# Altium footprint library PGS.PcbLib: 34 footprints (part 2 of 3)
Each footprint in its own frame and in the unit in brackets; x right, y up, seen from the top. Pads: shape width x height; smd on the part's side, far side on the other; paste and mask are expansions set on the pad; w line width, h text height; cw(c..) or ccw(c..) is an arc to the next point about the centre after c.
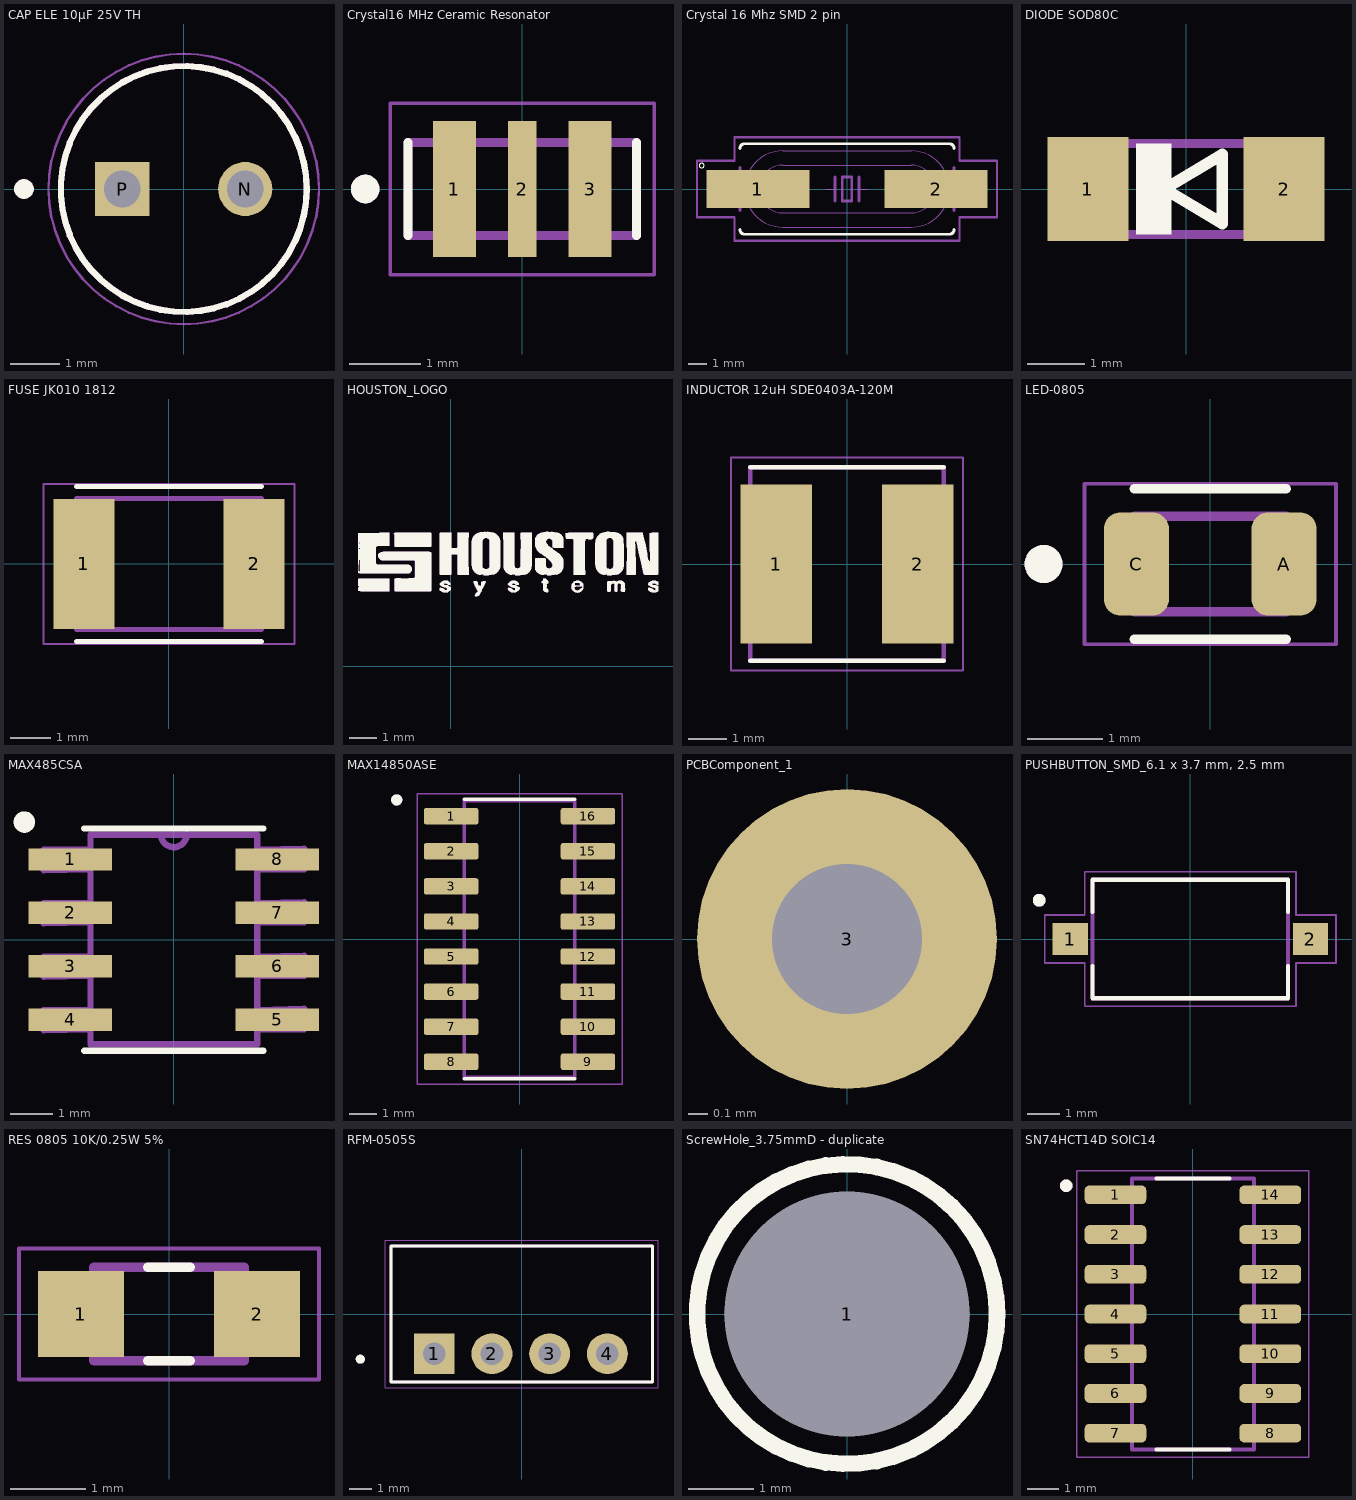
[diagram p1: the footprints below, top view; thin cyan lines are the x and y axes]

## CAP ELE 10µF 25V TH [mm] "10µF 25V Aluminum Electrolytic Capacitors Radial Lead Type THT, Dia-5mm, Pitch-2mm ECEA1EN100UI"
pads (2):
  round 1.1 hole 0.75: N(1.25,0)
  rect 1.1x1.1 hole 0.75: P(-1.25,0)
Top Overlay:
  circle w0.127: c0,0 r2.5
  circle w0.2: c-3.25,0 r0.1
Mechanical 13:
  circle w0.127: c0,0 r2.5
  circle w0.2: c-3.25,0 r0.1
Mechanical 15:
  circle w0.05: c0,0 r2.75
3D body "step_temp.STEP": height 11, standoff -17, extent -2.5,-2.498 2.5,2.498

## Crystal16 MHz Ceramic Resonator [mm] "Crystal 16 MHz Ceramic Resonator Built SMT in Capacitor 15 pF Â±0.3% -20Â°C ~ 80Â°C Surface Mount-CSTCE16M0V53-R0CSTCE16M0V53-R0"
pads (3):
  rect 0.6x1.9 smd: 1(-0.95,0) 3(0.95,0)
  rect 0.4x1.9 smd: 2(0,0)
Top Overlay:
  circle w0.2: c-2.2,0 r0.1
  lines w0.127: -1.6,-0.65 -1.6,0.65 ; 1.6,-0.65 1.6,0.65
Mechanical 13:
  circle w0.2: c-2.2,0 r0.1
  lines w0.127: -1.6,-0.65 1.6,-0.65 1.6,0.65 -1.6,0.65 -1.6,-0.65
Mechanical 15:
  lines w0.05: -1.85,-1.2 1.85,-1.2 1.85,1.2 -1.85,1.2 -1.85,-1.2
3D body "step_temp.STEP": height 1, standoff 0, extent -1.6,-0.65 1.6,0.65

## Crystal 16 Mhz SMD 2 pin [mm] "16 MHz Â±30ppm Crystal 20pF 60 Ohms HC-49/US FOXSDLF/128-20 16 Mhz Crystal SMD –CSM-4ALX(28ALX) SMT12.5mmX4.85mmX4mm"
pads (2):
  rect 5.5x2 smd: 1(-4.75,0) 2(4.75,0)
Top Overlay:
  circle w0: c-7.75,1.25 r0.127
  lines w0.152: -5.715,-2.159 ccw(c-5.461,-2.159) -5.461,-2.413 5.461,-2.413 ccw(c5.461,-2.159) 5.715,-2.159 ; -5.715,2.159 cw(c-5.461,2.159) -5.461,2.413 5.461,2.413 cw(c5.461,2.159) 5.715,2.159
Mechanical 13:
  lines w0.051: -1.143,0 -0.635,0 ; 0.635,0 1.143,0 ; -5.114,-1.136 ccw(c-3.429,0) -3.429,-2.032 3.429,-2.032 ccw(c3.429,0) 5.113,-1.136 ccw(c3.429,0) 5.114,1.136 ccw(c3.429,0) 3.429,2.032 -3.429,2.032 ccw(c-3.429,0) -5.114,1.136 ccw(c-3.429,0) -5.114,-1.136 ; -3.986,-1.141 ccw(c-3.429,0) -3.429,-1.27 3.429,-1.27 ccw(c3.429,0) 3.986,-1.141 ccw(c3.429,0) 3.986,1.141 ccw(c3.429,0) 3.429,1.27 -3.429,1.27 ccw(c-3.429,0) -3.986,1.141 ccw(c-3.429,0) -3.986,-1.141
  lines w0.152: -5.715,-1.143 -5.715,1.143 ; -5.715,-0.381 -6.477,-0.381 -6.477,0.381 -5.715,0.381 ; -0.635,-0.635 -0.635,0 -0.635,0.635 ; 0.635,-0.635 0.635,0 0.635,0.635 ; 5.715,-1.143 5.715,-0.381 ; 5.715,1.143 5.715,0.381 ; 5.715,-0.381 5.715,0.381 ; 5.715,-0.381 6.477,-0.381 6.477,0.381 5.715,0.381 ; -0.254,-0.635 -0.254,0.635 0.254,0.635 0.254,-0.635 -0.254,-0.635
Mechanical 15:
  lines w0.127: -8,-1.5 -8,1.5 -6,1.5 -6,2.75 6,2.75 6,1.5 8,1.5 8,-1.5 6,-1.5 6,-2.75 -6,-2.75 -6,-1.5 -8,-1.5
3D body "step_temp.STEP": height 4.5, standoff 0, extent -6.75,-2.5 6.75,2.5

## DIODE SOD80C [mm] "Diode Standard 75V 200mA _DC_ SMT LLDS; MiniMelf DIODE SOD80C PMLL4148L"
pads (2):
  rect 1.4x1.8 smd: 1(-1.7,0) 2(1.7,0)
Top Overlay:
  region: -0.254,-0.788 -0.864,-0.788 -0.864,0.787 -0.254,0.787
  lines w0.203: -0.373,0 0.627,0.6 0.627,-0.6 -0.373,0
Mechanical 13:
  region: -1.295,-0.865 -1.857,-0.865 -1.857,0.864 -1.295,0.864
  region: 1.854,-0.865 1.298,-0.865 1.298,0.864 1.854,0.864
  lines w0.152: -1.321,-0.787 1.321,-0.787 ; -1.321,0.787 1.321,0.787
3D body "BZT55C75-GS08.STEP": height 0.8, standoff -0.8, extent -1.75,-0.762 1.75,0.805

## FUSE JK010 1812 [mm] "FUSE JK010 Polymeric PTC Resettable Fuse 60V 100 mA 0.8W Ih SMT 1812 (4532 Metric), Concave HUAAN MF-MSMF010-60V"
pads (2):
  rect 1.5x3.2 smd: 1(-2.1,0) 2(2.1,0)
Top Overlay:
  lines w0.127: -2.275,-1.913 2.275,-1.913 ; -2.275,1.913 2.275,1.913
Mechanical 13:
  lines w0.127: -2.275,-1.62 -2.275,1.62 2.275,1.62 2.275,-1.62 -2.275,-1.62
Mechanical 15:
  lines w0.05: -3.1,-1.977 3.1,-1.977 3.1,1.977 -3.1,1.977 -3.1,-1.977
3D body "step_temp.STEP": height 0.85, standoff 0, extent -2.275,-1.62 2.275,1.62

## HOUSTON_LOGO [mm]
Top Overlay:
  drawing of 26 lines, arcs and shapes, not listed
Mechanical 13:
  drawing of 26 lines, arcs and shapes, not listed

## INDUCTOR 12uH SDE0403A-120M [mm] "INDUCTOR_2020(5.5mmX4.5mm)  SMT INDUCTOR 12uH SDE0403A-120M LQH5BPB4R7NT0L"
pads (2):
  rect 1.85x4.1 smd: 1(-1.825,0) 2(1.825,0)
Top Overlay:
  lines w0.127: -2.5,-2.5 2.5,-2.5 ; -2.5,2.5 2.5,2.5
Mechanical 13:
  lines w0.127: -2.5,-2.5 2.5,-2.5 2.5,2.5 -2.5,2.5 -2.5,-2.5
Mechanical 15:
  lines w0.05: -3,-2.75 3,-2.75 3,2.75 -3,2.75 -3,-2.75
3D body "LQH5BPN100M38L.STEP": height 4, standoff 0, extent -2.45,-2.45 2.45,2.45

## LED-0805 [mm] "Red 640nm LED Indication - Discrete 1.85V 0805 (2012 Metric) SMT APT2012SRCPRV"
pads (2):
  rrect50% 0.86x1.36 smd: A(0.975,0) C(-0.975,0)
Top Overlay:
  circle w0.3: c-2.2,0 r0.1
  lines w0.127: -1,-0.995 1,-0.995 ; -1,0.995 1,0.995
Mechanical 13:
  circle w0.3: c-2.2,0 r0.1
  lines w0.127: -1,-0.63 1,-0.63 1,0.63 -1,0.63 -1,-0.63
Mechanical 15:
  lines w0.05: -1.66,-1.059 1.66,-1.059 1.66,1.059 -1.66,1.059 -1.66,-1.059
3D body "step_temp.STEP": height 0.75, standoff 0, extent -1,-0.625 1,0.625

## MAX485CSA [mil] "MAX485CSA-RS-485/RS-422 Transceivers, SOIC-8 SMT"
pads (8):
  rect 78x21 smd: 1(-97,75) 2(-97,25) 3(-97,-25) 4(-97,-75) 5(97,-75) 6(97,-25) 7(97,25) 8(97,75)
Top Overlay:
  circle w10: c-140,110 r5
  lines w6: -84,-104 84,-104 ; -84,104 84,104
Mechanical 13:
  lines w6: -12,98.08 ccw(c0,98.5) 12,98.92 ; -122,-85 -78,-84 -78,-66 -122,-66 -122,-85 ; -122,-35 -78,-34 -78,-16 -122,-16 -122,-35 ; -122,15 -78,16 -78,34 -122,34 -122,15 ; -122,65 -78,66 -78,84 -122,84 -122,65 ; -78,-98 -78,98 -12,98 78,98 78,-98 -78,-98 ; 78,-84 122,-84 122,-65 78,-66 78,-84 ; 78,-34 122,-34 122,-15 78,-16 78,-34 ; 78,16 122,16 122,35 78,34 78,16 ; 78,66 122,66 122,85 78,84 78,66
3D body "step_temp.STEP": height 68.9, standoff 0, extent -118.11,-96.46 118.11,96.46

## MAX14850ASE [mm] "MAX14850ASE SOIC16 Six-Channel SMT Digital Isolator SOIC127P600X175-16N"
pads (16):
  rrect25% 1.97x0.59 smd: 1(-2.475,4.445) 2(-2.475,3.175) 3(-2.475,1.905) 4(-2.475,0.635) 5(-2.475,-0.635) 6(-2.475,-1.905) 7(-2.475,-3.175) 8(-2.475,-4.445) 9(2.475,-4.445) 10(2.475,-3.175) 11(2.475,-1.905) 12(2.475,-0.635) 13(2.475,0.635) 14(2.475,1.905) 15(2.475,3.175) 16(2.475,4.445)
Top Overlay:
  circle w0.2: c-4.445,5.035 r0.1
  lines w0.127: -2,-5.06 2,-5.06 ; -2,5.06 2,5.06
Mechanical 13:
  circle w0.2: c-4.445,5.035 r0.1
  lines w0.127: -2,-5 2,-5 2,5 -2,5 -2,-5
Mechanical 15:
  lines w0.05: -3.71,-5.25 3.71,-5.25 3.71,5.25 -3.71,5.25 -3.71,-5.25
3D body "step_temp.STEP": height 1.75, standoff 0, extent -3,-4.95 3,4.95

## PCBComponent_1 [mil]
pads (1):
  round 60 hole 30: 3(0,0)

## PUSHBUTTON_SMD_6.1 x 3.7 mm, 2.5 mm [mm] "6.1 x 3.7 mm, 2.5 mm Actuator Height, 260 gf, Red, SMT, SPST, Tactile Switch, TS09-63-25-R-260-SMT-TR"
height 2.5
pads (2):
  rect 1.1x1 smd: 1(-3.75,0) 2(3.75,0)
Top Overlay:
  circle w0.2: c-4.72,1.21 r0.1
  lines w0.127: -3.05,-0.85 -3.05,-1.85 3.05,-1.85 3.05,-0.85 ; -3.05,0.85 -3.05,1.85 3.05,1.85 3.05,0.85
Mechanical 13:
  circle w0.2: c-4.72,1.21 r0.1
  lines w0.127: -3.05,-1.85 3.05,-1.85 3.05,1.85 -3.05,1.85 -3.05,-1.85
Mechanical 15:
  lines w0.05: -4.55,-0.75 -4.55,0.75 -3.3,0.75 -3.3,2.1 3.3,2.1 3.3,0.75 4.55,0.75 4.55,-0.75 3.3,-0.75 3.3,-2.1 -3.3,-2.1 -3.3,-0.75 -4.55,-0.75
3D body "step_temp.STEP": height 2.5, standoff -0.05, extent -4.05,-1.85 4.05,1.85

## RES 0805 10K/0.25W 5% [mm] "RESISTOR, THICK FILM, 10K, 5%, 0805, SMT FULL REEL Product Range:PANASONIC - ERJ Series"
height 0.55
pads (2):
  rect 1.15x1.15 smd: 1(-1.175,0) 2(1.175,0)
Top Overlay:
  lines w0.127: -0.28,-0.625 0.28,-0.625 ; -0.28,0.625 0.28,0.625
Mechanical 13:
  lines w0.127: -1,-0.625 -1,0.625 1,0.625 1,-0.625 -1,-0.625
Mechanical 15:
  lines w0.05: -2,-0.875 -2,0.875 2,0.875 2,-0.875 -2,-0.875
3D body "step_temp.STEP": height 0.7, standoff 0, extent -1,-0.625 1,0.625

## RFM-0505S [mm] "DC-DC Converter/Isolator, SIP4, THT S/T 1kV unreg, Single Output, 1W, 5V Out, RFM Series RFM-0505S"
height 10
pads (4):
  rect 1.8x1.8 hole 1: 1(-3.85,-1.75)
  round 1.8 hole 1: 2(-1.31,-1.75) 3(1.23,-1.75) 4(3.77,-1.75)
Top Overlay:
  circle w0.2: c-7.11,-1.99 r0.1
  lines w0.127: -5.75,-3 5.75,-3 5.75,3 -5.75,3 -5.75,-3
Mechanical 13:
  circle w0.2: c-7.1,-1.99 r0.1
  lines w0.127: -5.75,-3 5.75,-3 5.75,3 -5.75,3 -5.75,-3
Mechanical 15:
  lines w0.05: -6,-3.25 6,-3.25 6,3.25 -6,3.25 -6,-3.25
3D body "step_temp.STEP": height 9.5, standoff -4.6, extent -5.75,-3 5.75,3

## ScrewHole_3.75mmD - duplicate [mm] "SCREW HEAD DIA 4.5MM, SREW LEG DIA 3 MM"
pads (1):
  round 3.75 hole 3.75 unplated: 1(0,0)
Top Overlay:
  circle w0.254: c0,0 r2.3

## SN74HCT14D SOIC14 [mm] "SN74HCT14D SOIC14 6-ch, 4.5V to 5.5V SMT inverters with Schmitt-Trigger inputs"
pads (14):
  rrect50% 1.97x0.6 smd: 1(-2.475,3.81) 2(-2.475,2.54) 3(-2.475,1.27) 4(-2.475,0) 5(-2.475,-1.27) 6(-2.475,-2.54) 7(-2.475,-3.81) 8(2.475,-3.81) 9(2.475,-2.54) 10(2.475,-1.27) 11(2.475,0) 12(2.475,1.27) 13(2.475,2.54) 14(2.475,3.81)
Top Overlay:
  circle w0.2: c-4.05,4.1 r0.1
  lines w0.127: -1.17,-4.325 1.17,-4.325 ; -1.17,4.325 1.17,4.325
Mechanical 13:
  circle w0.2: c-4.05,4.1 r0.1
  lines w0.127: -1.95,-4.325 -1.95,4.325 1.95,4.325 1.95,-4.325 -1.95,-4.325
Mechanical 15:
  lines w0.05: -3.71,-4.575 -3.71,4.575 3.71,4.575 3.71,-4.575 -3.71,-4.575
3D body "step_temp.STEP": height 1.75, standoff 0, extent -3,-4.325 3,4.325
